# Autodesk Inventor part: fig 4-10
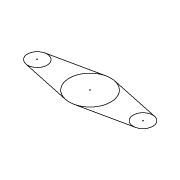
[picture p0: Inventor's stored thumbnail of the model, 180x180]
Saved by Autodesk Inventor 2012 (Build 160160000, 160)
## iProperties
Created: 2005-02
Part Number: fig 4-10
Document SubType Name: Modeling
Designer: CADCIM
Manufacturer: Standard
Standards Organization: Custom
Density: 1 g/cm^3
Material: Default
Author: CADCIM
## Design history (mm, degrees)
sketch "Sketch1"
  geometry: L1 (-33.874, 5.844)-(-2.722, 12.469); L2 (2.595, 12.472)-(33.871, 5.852); L3 (-33.884, -5.902)-(-2.745, -12.585); L4 (2.595, -12.592)-(33.871, -5.972); A1 r 12.81 centre (-0.057, -0.06) between (-2.722, 12.469) and (2.595, 12.472); A2 r 6.006 centre (-32.624, -0.03) between (-33.874, 5.844) and (-33.884, -5.902); A3 r 6.043 centre (32.619, -0.06) between (33.871, 5.852) and (33.871, -5.972)
  constraints: 8 end point, 8 point on circle, 8 tangent, 3 centre point, 1 other
